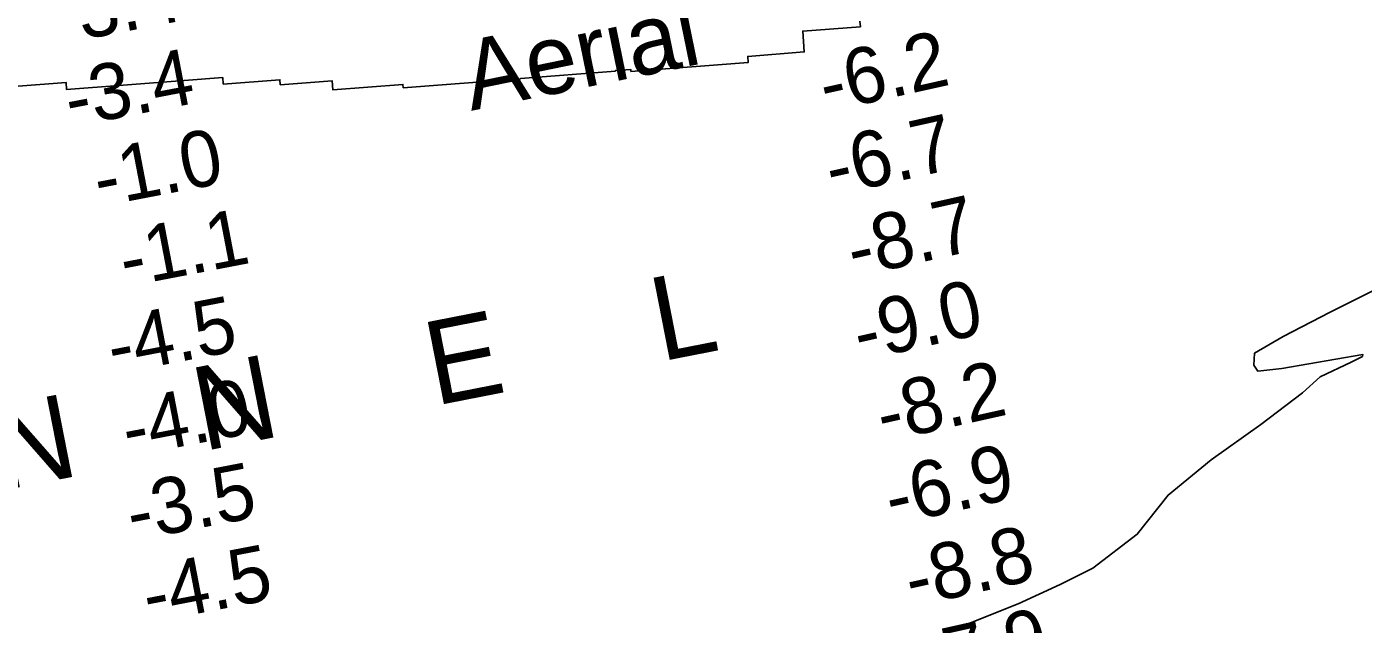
# Model space of a CAD drawing. Extents: x 3180038 to 3217926, y 922069 to 947485.
# Drawn here: x 3190456 to 3192054, y 932483 to 933197 of the extents above; entities that cross this region are included whole.
import ezdxf

# ---------------------------------------------------------------- set-up
doc = ezdxf.new("R2010")
doc.units = 0
for name, color, linetype in [('V-RIVR-EDGE', 7, 'Continuous'), ('V-RIVR-IDEN', 7, 'Continuous'), ('V-RIVR-RANG', 7, 'Continuous'), ('V-ROAD-CNTR', 7, 'Continuous'), ('V-RRAP-RVMT', 7, 'Continuous')]:
    doc.layers.add(name, color=color, linetype=linetype)

msp = doc.modelspace()

# ---------------------------------------------------------------- linework, layer by layer
at = {"layer": 'V-RIVR-EDGE'}
msp.add_lwpolyline([(3191574.4, 932481.2), (3191641.4, 932507.5), (3191691.6, 932530.6), (3191730.5, 932550.4), (3191783.5, 932590.8), (3191820.3, 932637.7), (3191871.7, 932679.6), (3191931.2, 932722.1), (3191980.9, 932759.8), (3192002, 932779.1), (3192039.3, 932796.3), (3192052.8, 932803.3), (3192053.3, 932805.5), (3191956.2, 932789), (3191927.6, 932785.8), (3191922.7, 932792.8), (3191923.8, 932807.4), (3191957.9, 932827.3), (3192014.1, 932856.3), (3192081.6, 932890.1)], dxfattribs=at)
at = {"layer": 'V-ROAD-CNTR'}
msp.add_spline([(3190883.1, 931626), (3191324.7, 931711.5), (3191783.2, 931784.7), (3192184, 931861.5), (3192450.5, 931911.8), (3192534, 931939.4), (3192579.2, 931975), (3192650.8, 932051.8), (3192722.8, 932059.3), (3192919.2, 932122.2), (3193196.7, 932214.3), (3193390.7, 932283.3), (3193596.7, 932381.4), (3193810.3, 932493.3), (3193961.5, 932582.8), (3194195.7, 932716), (3194388.9, 932830.6), (3194615.4, 932953.5), (3194773.5, 933009.2), (3194936.2, 933060.2), (3195089.6, 933092.9), (3195267.4, 933093.6), (3195362.5, 933097.1), (3195546, 933098.8), (3195769.9, 933097.4), (3195942.4, 933091.9), (3196104.9, 933096.2), (3196211.3, 933092.6), (3196377, 933082), (3196525.9, 933080.9), (3196707.8, 933088), (3196883.4, 933088), (3197078.6, 933094.3), (3197228.2, 933084.5), (3197336.8, 933053.8), (3197413.5, 933012.4), (3197553.8, 932960.6), (3197689.8, 932913), (3197822.2, 932876.4), (3197956.7, 932845.7), (3198116.1, 932804.1)], degree=3, dxfattribs=at)
at = {"layer": 'V-RRAP-RVMT'}
msp.add_lwpolyline([(3191452.2, 933203.9), (3191452.7, 933197.3), (3191383.8, 933192), (3191385.7, 933167.1), (3191318.1, 933161.9), (3191318.7, 933154.7), (3191178.5, 933143.9), (3191178.3, 933146.2), (3191160, 933144.8), (3191160, 933144.3), (3191046.7, 933135.6), (3191046.7, 933135.1), (3190906.4, 933124.4), (3190906.1, 933128.4), (3190822.1, 933122), (3190821.3, 933132.7), (3190759.5, 933128), (3190759, 933134), (3190691.3, 933128.8), (3190690.7, 933136.6), (3190644.4, 933133.1), (3190644.4, 933132.9), (3190504.1, 933122.1), (3190503.5, 933130.7), (3190441, 933125.9)], dxfattribs=at)

# ---------------------------------------------------------------- texts
at = {"layer": 'V-RIVR-IDEN'}
for s, height, rotation, p in [('Aerial', 83, 11.581, (3190987.6, 933096.7)), ('C     H     A     N    N     E     L', 100, 11.0847, (3189602.6, 932481.4))]:
    msp.add_text(s, height=height, rotation=rotation, dxfattribs=at).set_placement(p)
at = {"layer": 'V-RIVR-RANG'}
for s, rotation, p in [('3.4', 10.8806, (3190522.8, 933181.6)), ('-6.2', 12.5894, (3191411.4, 933094.8)), ('-3.4', 10.8806, (3190508.5, 933077.3)), ('-6.7', 12.5894, (3191418.7, 932994.9)), ('-1.0', 10.8806, (3190543, 932982)), ('-8.7', 12.5894, (3191444.8, 932897.7)), ('-1.1', 10.8806, (3190574, 932886.2)), ('-9.0', 12.5894, (3191452.2, 932797.6)), ('-4.5', 10.8806, (3190559.5, 932781.6)), ('-8.2', 12.5894, (3191479.9, 932700.6)), ('-4.0', 10.8806, (3190577.1, 932683.2)), ('-6.9', 12.5894, (3191490, 932601.2)), ('-3.5', 10.8806, (3190582.5, 932582.7)), ('-8.8', 12.5894, (3191513.8, 932503.6)), ('-4.5', 10.8806, (3190601.7, 932484.6)), ('-7.9', 12.5894, (3191531, 932405.2))]:
    msp.add_text(s, height=67, rotation=rotation, dxfattribs=at).set_placement(p)

doc.saveas('drawing.dxf')
